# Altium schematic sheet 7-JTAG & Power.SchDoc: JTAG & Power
size B; CompanyName: NGRF; Address1: 2130 Howard Drive W; Address2: North Mankato, MN 56003; Address3: www.nextgenrf.com; Revision: 2; SheetNumber: 7; SheetTotal: 7; ProjName: BytePipe X9002_HDK; SystemEngineer: ELLIOT NELSON
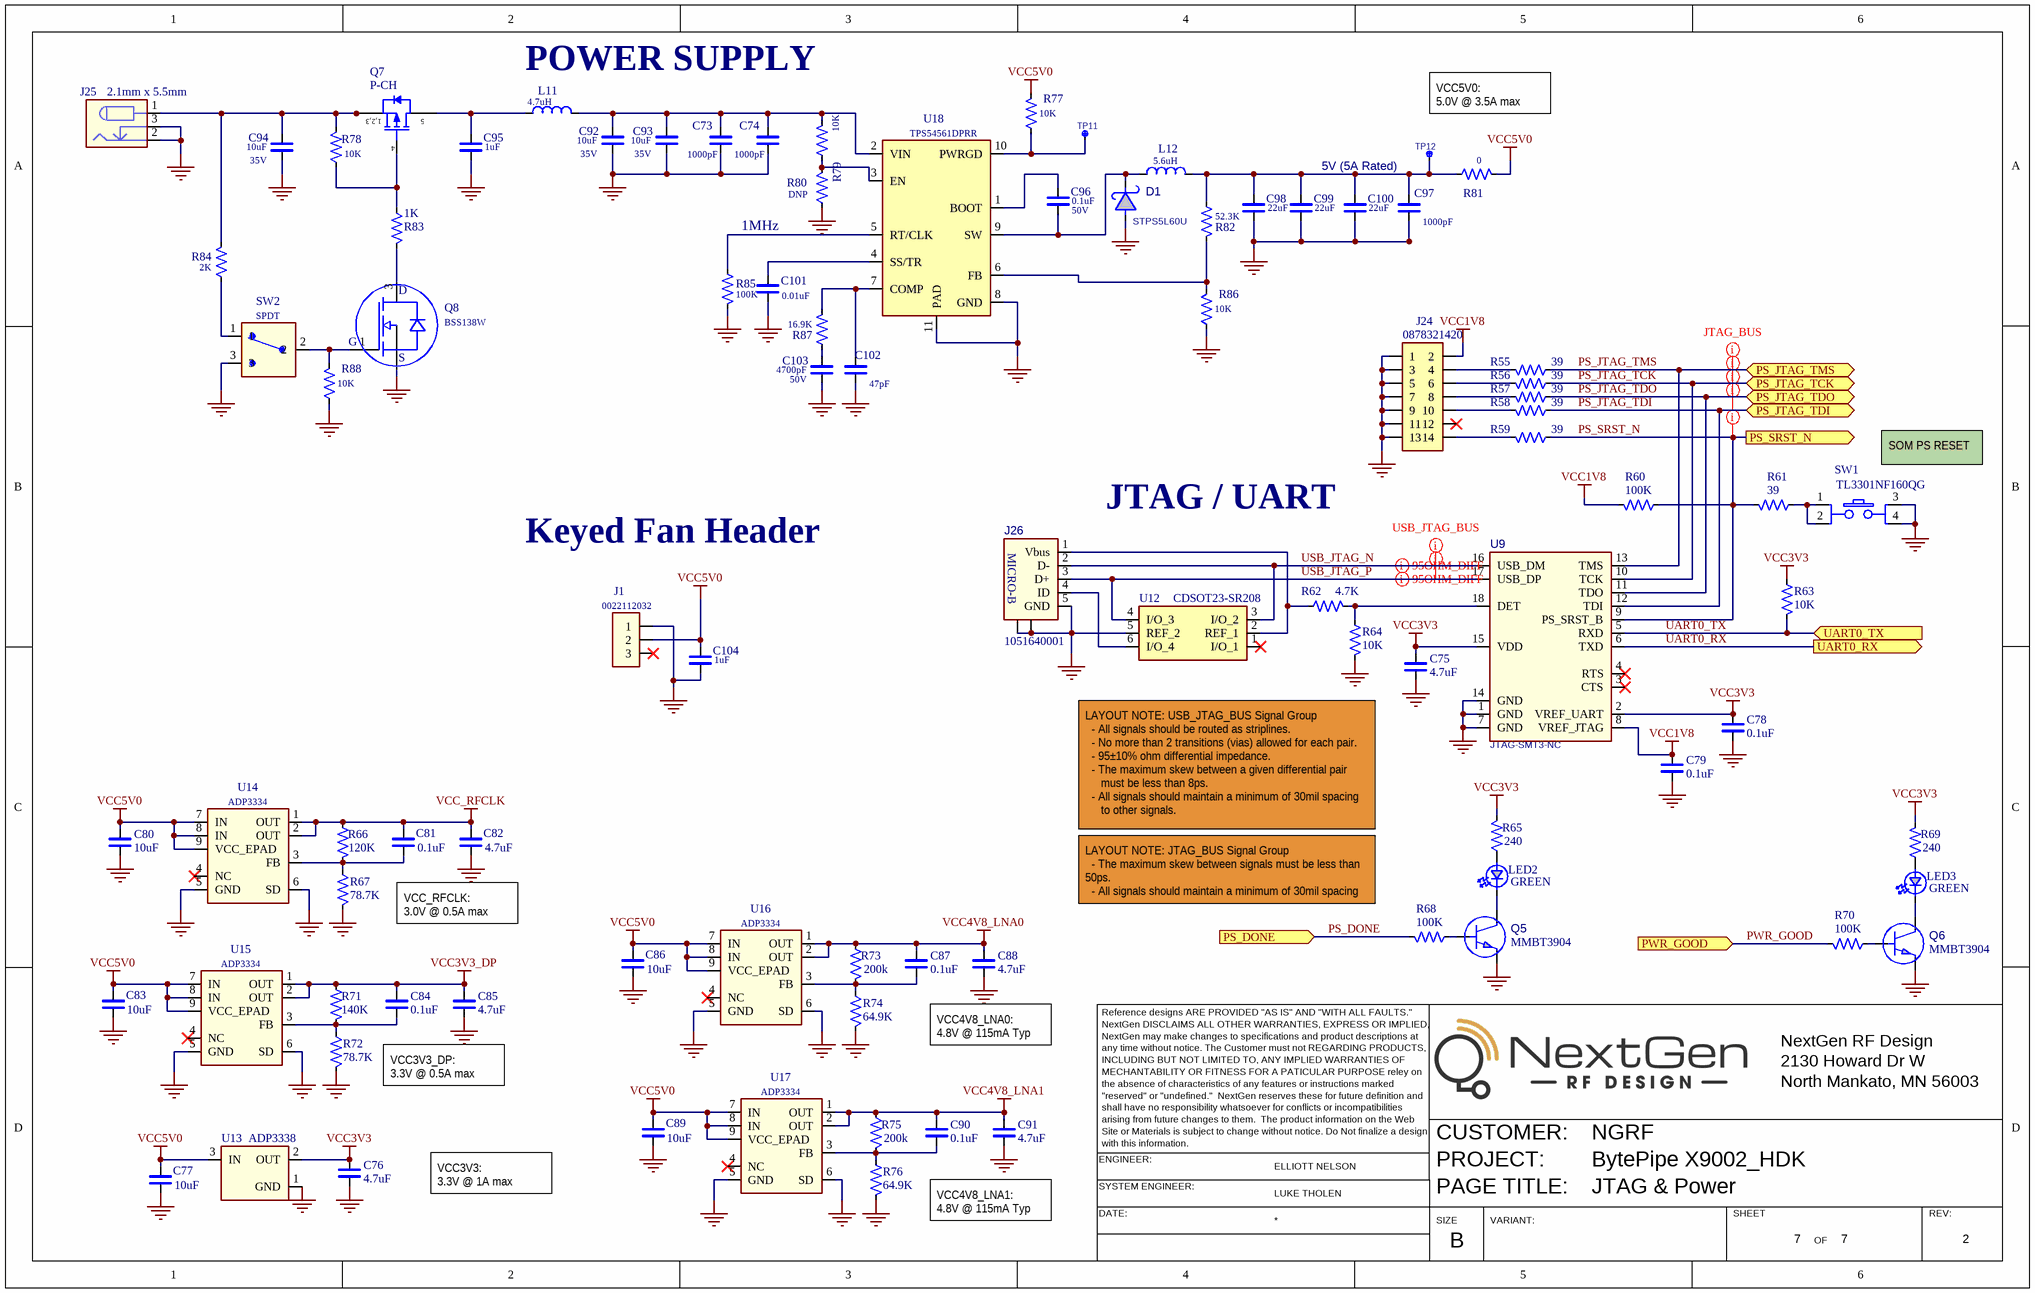
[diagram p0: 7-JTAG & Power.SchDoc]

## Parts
C73  value 1000pF  [SM/0402/CAP]
C74  value 1000pF  [SM/0402/CAP]
C75  value 4.7uF  [SM/0402/CAP]  (hidden comment: CAP_CERAMIC_0402)
C76  value 4.7uF  [SM/0402/CAP]  (hidden comment: CAP_CERAMIC_0402)
C77  value 10uF  [SM/0402/CAP]  (hidden comment: CAP_CERAMIC_0402)
C78  value 0.1uF  [SM/0402/CAP]  (hidden comment: CAP_CERAMIC_0402)
C79  value 0.1uF  [SM/0402/CAP]  (hidden comment: CAP_CERAMIC_0402)
C80  value 10uF  [SM/0402/CAP]  (hidden comment: CAP_CERAMIC_0402)
C81  value 0.1uF  [SM/0402/CAP]  (hidden comment: CAP_CERAMIC_0402)
C82  value 4.7uF  [SM/0402/CAP]  (hidden comment: CAP_CERAMIC_0402)
C83  value 10uF  [SM/0402/CAP]  (hidden comment: CAP_CERAMIC_0402)
C84  value 0.1uF  [SM/0402/CAP]  (hidden comment: CAP_CERAMIC_0402)
C85  value 4.7uF  [SM/0402/CAP]  (hidden comment: CAP_CERAMIC_0402)
C86  value 10uF  [SM/0402/CAP]  (hidden comment: CAP_CERAMIC_0402)
C87  value 0.1uF  [SM/0402/CAP]  (hidden comment: CAP_CERAMIC_0402)
C88  value 4.7uF  [SM/0402/CAP]  (hidden comment: CAP_CERAMIC_0402)
C89  value 10uF  [SM/0402/CAP]  (hidden comment: CAP_CERAMIC_0402)
C90  value 0.1uF  [SM/0402/CAP]  (hidden comment: CAP_CERAMIC_0402)
C91  value 4.7uF  [SM/0402/CAP]  (hidden comment: CAP_CERAMIC_0402)
C92  value 10uF  VOLT: 35V  [SM/0805/CAP]  (hidden comment: CAP_CERAMIC_0805)
C93  value 10uF  VOLT: 35V  [SM/0805/CAP]  (hidden comment: CAP_CERAMIC_0805)
C94  value 10uF  VOLT: 35V  [SM/0805/CAP]  (hidden comment: CAP_CERAMIC_0805)
C95  value 1uF  [SM/0603/CAP]  (hidden comment: CAP_CERAMIC_0603)
C96  value 0.1uF  VOLT: 50V  [SM/0402/CAP]  (hidden comment: CAP_CERAMIC_0402)
C97  value 1000pF  [SM/0402/CAP]
C98  value 22uF  [SM/0805/CAP]  (hidden comment: CAP_CERAMIC_0805)
C99  value 22uF  [SM/0805/CAP]  (hidden comment: CAP_CERAMIC_0805)
C100  value 22uF  [SM/0805/CAP]  (hidden comment: CAP_CERAMIC_0805)
C101  value 0.01uF  [SM/0402/CAP]
C102  value 47pF  [SM/0402/CAP]
C103  value 4700pF  VOLT: 50V  [SM/0402/CAP]
C104  value 1uF  [SM/0603/CAP]  (hidden comment: CAP_CERAMIC_0603)
D1  value STPS5L60U  [SM/DO-214AA/SMB_A]  (hidden comment: DIODE_SCHOTTKY SMB)
J1  0022112032  [CON/MLX/0022112032/3P]
J24  value 0878321420  [SM/CON/MLX/0878321420]  (hidden comment: CON_MOLEX_0878321420_14P)
J25  value 2.1mm x 5.5mm  [CON/WURTH/694106301002]  (hidden comment: CON_WURTH_694106301002)
J26  value 1051640001  [SM/CON/USB/MICRO B RA]  (hidden comment: CON_USB_MICRO-B_RA)
L11  value 4.7uH  [SM/IND/COILCRAFT/XAL4020]  (hidden comment: IND_COILCRAFT_XAL4020)
L12  value 5.6uH  [SM/IND/COILCRAFT/XAL7030]  (hidden comment: IND_COILCRAFT_XAL7030)
LED2  value GREEN  [SM/LED_0603]  (hidden comment: LED_0603)
LED3  value GREEN  [SM/LED_0603]  (hidden comment: LED_0603)
Q5  value MMBT3904  [SM/SOT23_A]  (hidden comment: TRANSISTOR_NPN_SOT23)
Q6  value MMBT3904  [SM/SOT23_A]  (hidden comment: TRANSISTOR_NPN_SOT23)
Q7  value P-CH  [SM/POWERPAK/VISHAY/SO-8]  (hidden comment: MOSFET P-CH 20V 60A PPAK SO-8)
Q8  value BSS138W  [SM/SOT323_A]  (hidden comment: FET_N-CHANNEL_SC70)
R55  value 39  [SM/0402/RES]  (hidden comment: RES_0402_A)
R56  value 39  [SM/0402/RES]  (hidden comment: RES_0402_A)
R57  value 39  [SM/0402/RES]  (hidden comment: RES_0402_A)
R58  value 39  [SM/0402/RES]  (hidden comment: RES_0402_A)
R59  value 39  [SM/0402/RES]  (hidden comment: RES_0402_A)
R60  value 100K  [SM/0402/RES]  (hidden comment: RES_0402_A)
R61  value 39  [SM/0402/RES]  (hidden comment: RES_0402_A)
R62  value 4.7K  [SM/0402/RES]  (hidden comment: RES_0402_A)
R63  value 10K  [SM/0402/RES]  (hidden comment: RES_0402_A)
R64  value 10K  [SM/0402/RES]  (hidden comment: RES_0402_A)
R65  value 240  [SM/0402/RES]  (hidden comment: RES_0402_A)
R66  value 120K  [SM/0402/RES]  (hidden comment: RES_0402_A)
R67  value 78.7K  [SM/0402/RES]  (hidden comment: RES_0402_A)
R68  value 100K  [SM/0402/RES]  (hidden comment: RES_0402_A)
R69  value 240  [SM/0402/RES]  (hidden comment: RES_0402_A)
R70  value 100K  [SM/0402/RES]  (hidden comment: RES_0402_A)
R71  value 140K  [SM/0402/RES]  (hidden comment: RES_0402_A)
R72  value 78.7K  [SM/0402/RES]  (hidden comment: RES_0402_A)
R73  value 200k  [SM/0402/RES]  (hidden comment: RES_0402_A)
R74  value 64.9K  [SM/0402/RES]  (hidden comment: RES_0402_A)
R75  value 200k  [SM/0402/RES]  (hidden comment: RES_0402_A)
R76  value 64.9K  [SM/0402/RES]  (hidden comment: RES_0402_A)
R77  value 10K  [SM/0402/RES]  (hidden comment: RES_0402_A)
R78  value 10K  [SM/0402/RES]  (hidden comment: RES_0402_A)
R79  value 10K  [SM/0402/RES]  (hidden comment: RES_0402_A)
R80  value DNP  [SM/0402/RES]  (hidden comment: RES_0402_A)
R81  value 0  [SM/0805/RES]  (hidden comment: RES_0805_A)
R82  value 52.3K  [SM/0402/RES]  (hidden comment: RES_0402_A)
R83  value 1K  [SM/0402/RES]  (hidden comment: RES_0402_A)
R84  value 2K  [SM/0402/RES]  (hidden comment: RES_0402_A)
R85  value 100K  [SM/0402/RES]  (hidden comment: RES_0402_A)
R86  value 10K  [SM/0402/RES]  (hidden comment: RES_0402_A)
R87  value 16.9K  [SM/0402/RES]  (hidden comment: RES_0402_A)
R88  value 10K  [SM/0402/RES]  (hidden comment: RES_0402_A)
SW1  value TL3301NF160QG  [SM/SWITCH/E-SWITCH/SPST]  (hidden comment: SWITCH_E-SWITCH_TACTILE_SPST)
SW2  value SPDT  [SWITCH/NIDEC/SPDT/AS1D-2M-10-Z]  (hidden comment: AS1D-2M-10-Z)
TP11  TESTPOINT_030  [SM/TESTPOINT/30MIL]  (value not drawn)  (no BOM)
TP12  TESTPOINT_030  [SM/TESTPOINT/30MIL]  (value not drawn)  (no BOM)
U9  value JTAG-SMT3-NC  [SM/MODULE/DIGILENT/JTAG-SMT3]  (hidden comment: MODULE_JTAG-SMT3-NC_18P)
U12  value CDSOT23-SR208  [SM/SOT23-6_C]  (hidden comment: TVS_CDSOT23_SOT23-6_C)
U13  value ADP3338  [SM/SOT223-3_B]  (hidden comment: REG_ADP3338_SOT223-3)
U14  value ADP3334  [SM/DFN8/3x3MM_B]  (hidden comment: REG_ADP334_DFN-8)
U15  value ADP3334  [SM/DFN8/3x3MM_B]  (hidden comment: REG_ADP334_DFN-8)
U16  value ADP3334  [SM/DFN8/3x3MM_B]  (hidden comment: REG_ADP334_DFN-8)
U17  value ADP3334  [SM/DFN8/3x3MM_B]  (hidden comment: REG_ADP334_DFN-8)
U18  value TPS54561DPRR  [SM/WSON10/4x4MM_A]  (hidden comment: REG_TPS54561_WSON-10)

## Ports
PS_DONE (in), PS_JTAG_TCK (bidir), PS_JTAG_TDI (bidir), PS_JTAG_TDO (bidir), PS_JTAG_TMS (bidir), PS_SRST_N (out), PWR_GOOD (in), UART0_RX (out), UART0_TX (in)

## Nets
GND: C73.1(N1) C74.1(N1) C75.2(N2) C76.2(N2) C77.2(N2) C78.2(N2) C79.2(N2) C80.2(N2) C82.2(N2) C83.2(N2) C85.2(N2) C86.2(N2) C88.2(N2) C89.2(N2) C91.2(N2) C92.2(N2) C93.2(N2) C94.2(N2) C95.2(N2) C97.1(N1) C98.2(N2) C99.2(N2) C100.2(N2) C101.1(N1) C102.1(N1) C103.2(N2) C104.2(N2) D1.2(A) J1.1 J24.1 J24.3 J24.5 J24.7 J24.9 J24.11 J24.13 J25.2 J25.3 J26.5(GND) J26.SH J26.TH Q5.2(E) Q6.2(E) Q8.2(SOURCE) R64.2 R67.1 R72.1 R74.1 R76.1 R80.1 R85.2 R86.2 R88.2 SW1.3 SW1.4 SW2.3 U9.1(GND) U9.7(GND) U9.14(GND) U12.5(REF_2) U13.1(GND) U14.5(GND) U14.6(SD) U15.5(GND) U15.6(SD) U16.5(GND) U16.6(SD) U17.5(GND) U17.6(SD) U18.8(GND) U18.11(PAD)
VCC1V8: C79.1(N1) J24.2 R60.2 U9.8(VREF_JTAG)
VCC3V3: C75.1(N1) C76.1(N1) C78.1(N1) R63.1 R65.1 R69.1 U9.2(VREF_UART) U9.15(VDD) U13.2(OUT)
VCC3V3_DP: C84.1(N1) C85.1(N1) R71.2 U15.1(OUT) U15.2(OUT)
VCC4V8_LNA0: C87.1(N1) C88.1(N1) R73.2 U16.1(OUT) U16.2(OUT)
VCC4V8_LNA1: C90.1(N1) C91.1(N1) R75.2 U17.1(OUT) U17.2(OUT)
VCC5V0: C77.1(N1) C80.1(N1) C83.1(N1) C86.1(N1) C89.1(N1) C104.1(N1) J1.2 R77.1 R81.2 U13.3(IN) U14.7(IN) U14.8(IN) U14.9(VCC_EPAD) U15.7(IN) U15.8(IN) U15.9(VCC_EPAD) U16.7(IN) U16.8(IN) U16.9(VCC_EPAD) U17.7(IN) U17.8(IN) U17.9(VCC_EPAD)
VCC_RFCLK: C81.1(N1) C82.1(N1) R66.2 U14.1(OUT) U14.2(OUT)
PS_DONE: R68.2 ; port PS_DONE
PS_JTAG_TCK: R56.1 U9.10(TCK) ; port PS_JTAG_TCK
PS_JTAG_TDI: R58.1 U9.12(TDI) ; port PS_JTAG_TDI
PS_JTAG_TDO: R57.1 U9.11(TDO) ; port PS_JTAG_TDO
PS_JTAG_TMS: R55.1 U9.13(TMS) ; port PS_JTAG_TMS
PS_SRST_N: R59.1 R60.1 R61.2 U9.9(PS_SRST_B) ; port PS_SRST_N
PWR_GOOD: R70.2 ; port PWR_GOOD
UART0_RX: U9.6(TXD) ; port UART0_RX
UART0_TX: R63.2 U9.5(RXD) ; port UART0_TX
USB_JTAG_N: J26.2(D-) U9.16(USB_DM) U12.3(I/O_2)
USB_JTAG_P: J26.3(D+) U9.17(USB_DP) U12.4(I/O_3)
NetC73_2: C73.2(N2) C74.2(N2) C92.1(N1) C93.1(N1) L11.2(N2) R79.2 U18.2(VIN)
NetC81_2: C81.2(N2) R66.1 R67.2 U14.3(FB)
NetC84_2: C84.2(N2) R71.1 R72.2 U15.3(FB)
NetC87_2: C87.2(N2) R73.1 R74.2 U16.3(FB)
NetC90_2: C90.2(N2) R75.1 R76.2 U17.3(FB)
NetC94_1: C94.1(N1) J25.1 Q7.1(SOURCE) Q7.2(SOURCE) Q7.3(SOURCE) R78.1 R84.1
NetC95_1: C95.1(N1) L11.1(N1) Q7.5(DRAIN)
NetC96_1: C96.1(N1) U18.1(BOOT)
NetC96_2: C96.2(N2) D1.1(K) L12.1(N1) U18.9(SW)
NetC97_2: C97.2(N2) C98.1(N1) C99.1(N1) C100.1(N1) L12.2(N2) R81.1 R82.2 TP12.1(N1)
NetC101_2: C101.2(N2) U18.4(SS/TR)
NetC102_2: C102.2(N2) R87.2 U18.7(COMP)
NetC103_1: C103.1(N1) R87.1
NetJ24_4: J24.4 R55.2
NetJ24_6: J24.6 R56.2
NetJ24_8: J24.8 R57.2
NetJ24_10: J24.10 R58.2
NetJ24_14: J24.14 R59.2
NetJ26_1: J26.1(Vbus) R62.1 U12.2(REF_1)
NetJ26_4: J26.4(ID) U12.6(I/O_4)
NetLED2_1: LED2.1(C) Q5.3(C)
NetLED2_2: LED2.2(A) R65.2
NetLED3_1: LED3.1(C) Q6.3(C)
NetLED3_2: LED3.2(A) R69.2
NetQ5_1: Q5.1(B) R68.1
NetQ6_1: Q6.1(B) R70.1
NetQ7_4: Q7.4(GATE) R78.2 R83.1
NetQ8_1: Q8.1(GATE) R88.1 SW2.2
NetQ8_3: Q8.3(DRAIN) R83.2
NetR61_1: R61.1 SW1.1 SW1.2
NetR62_2: R62.2 R64.1 U9.18(DET)
NetR77_2: R77.2 TP11.1(N1) U18.10(PWRGD)
NetR79_1: R79.1 R80.2 U18.3(EN)
NetR82_1: R82.1 R86.1 U18.6(FB)
NetR84_2: R84.2 SW2.1
NetR85_1: R85.1 U18.5(RT/CLK)

Not connected (* = marked no-connect by the designer): J1 3*; J24 12*; U9 3(CTS)* 4(RTS)*; U12 1(I/O_1)*; U14 4(NC)*; U15 4(NC)*; U16 4(NC)*; U17 4(NC)*

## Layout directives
net class USB_JTAG_BUS: USB_JTAG_N, USB_JTAG_P
net class JTAG_BUS: PS_JTAG_TCK, PS_JTAG_TDI, PS_JTAG_TDO, PS_JTAG_TMS, PS_SRST_N
differential pair; Impedance: 90 Ohms; differential pair class 95OHM_DIFF: USB_JTAG_N, USB_JTAG_P

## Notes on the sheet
- (near L11) POWER SUPPLY
- VCC5V0:
  5.0V @ 3.5A max
- 1MHz
- 5V (5A Rated)
- (near SW1) SOM PS RESET
- Keyed Fan Header
- JTAG / UART
- LAYOUT NOTE: USB_JTAG_BUS Signal Group
  - All signals should be routed as striplines.
  - No more than 2 transitions (vias) allowed for each pair.
  - 95±10% ohm differential impedance.
  - The maximum skew between a given differential pair
  must be less than 8ps.
  - All signals should maintain a minimum of 30mil spacing
  to other signals.
- (near R68) LAYOUT NOTE: JTAG_BUS Signal Group
  - The maximum skew between signals must be less than 50ps.
  - All signals should maintain a minimum of 30mil spacing to
  other signals outside this signal group.
- VCC_RFCLK:
  3.0V @ 0.5A max
- VCC4V8_LNA0:
  4.8V @ 115mA Typ
- Reference designs ARE PROVIDED "AS IS" AND "WITH ALL FAULTS."
- NextGen DISCLAIMS ALL OTHER WARRANTIES, EXPRESS OR IMPLIED,
- NextGen may make changes to specifications and product descriptions at
- NextGen RF Design
- VCC3V3_DP:
  3.3V @ 0.5A max
- any time without notice. The Customer must not REGARDING PRODUCTS,
- INCLUDING BUT NOT LIMITED TO, ANY IMPLIED WARRANTIES OF
- MECHANTABILITY OR FITNESS FOR A PATICULAR PURPOSE reley on
- "reserved" or "undefined."  NextGen reserves these for future definition and
- the absence of characteristics of any features or instructions marked
- shall have no responsibility whatsoever for conflicts or incompatibilities
- 2130 Howard Dr W
- North Mankato, MN 56003
- ENGINEER:
- Site or Materials is subject to change without notice. Do Not finalize a design
- with this information.
- arising from future changes to them.  The product information on the Web
- ELLIOTT NELSON
- CUSTOMER:
- PROJECT:
- VCC3V3:
  3.3V @ 1A max
- VCC4V8_LNA1:
  4.8V @ 115mA Typ
- SYSTEM ENGINEER:
- DATE:
- LUKE THOLEN
- SIZE
- PAGE TITLE:
- VARIANT:
- SHEET
- OF
- REV:
- B

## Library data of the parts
C73 C74 C97 = CAP_CERAMIC_0402: CAP CER 1000PF 50V C0G/NP0 0402; TOL: 1%; OEM#: GRM1555C1H102FA01D; OEM NAME: Murata Electronics
C75 C76 C82 C85 C88 C91 = CAP_CERAMIC_0402: CAP CER 4.7UF 10V X5R 0402; TOL: ±20%; OEM#: CL05A475MP5NRNC; OEM NAME: Samsung
C77 C80 C83 C86 C89 = CAP_CERAMIC_0402: 10µF ±20% 10V Ceramic Capacitor X5R 0402 (1005 Metric); OEM#: CL05A106MP8NUB8; OEM NAME: Samsung
C78 C79 C81 C84 C87 C90 = CAP_CERAMIC_0402: CAP CER 0.1UF 25V X7R 0402; TOL: ±10%; OEM#: CL05B104KA5NNNC; OEM NAME: Samsung
C92 C93 = CAP_CERAMIC_0805: CAP CER 10UF 35V X5R 0805; OEM#: GRM21BR6YA106ME43L; OEM NAME: Murata Electronics; TOL: 20%
C94 = CAP_CERAMIC_0805: CAP CER 10UF 35V X5R 0805; OEM#: GMK212BBJ106MG-T; OEM NAME: Taiyo Yuden; TOL: 20%
C95 C104 = CAP_CERAMIC_0603: TOL: 10%; OEM#: GRT188R61H105KE13D; OEM NAME: Murata; VOLT: 50V
C96 = CAP_CERAMIC_0402: CAP CER 0.1UF 50V X7R 0402; TOL: 10%; OEM#: CGA2B3X7R1H104K050BB; OEM NAME: TDK Corporation
C98-C100 = CAP_CERAMIC_0805: CAP CER 22UF 16V X5R 0805; OEM#: GRM219R61C226ME15L; OEM NAME: Murata Electronics; TOL: 20%
C101 = CAP_CERAMIC_0402: CAP CER 10000PF 50V X7R 0402; TOL: 10%; OEM#: GCM155R71H103KA55J; OEM NAME: Murata Electronics
C102 = CAP_CERAMIC_0402: CAP CER 47PF 50V C0G/NP0 0402; TOL: 5%; OEM#: GCM1555C1H470JA16D; OEM NAME: Murata Electronics
C103 = CAP_CERAMIC_0402: CAP CER 4700PF 50V X7R 0402; TOL: 10%; OEM#: GRM155R71H472KA01J; OEM NAME: Murata
D1 = DIODE_SCHOTTKY SMB: DIODE SCHOTTKY 60V 5A SMB; OEM NAME: STMicroelectronics
J1 = CON_100SP_1X3P_MLX_KK100: Connector Header Through Hole 3 position 0.100" (2.54mm).  Molex KK 100 Series.
J24 = CON_MOLEX_0878321420_14P: Connector Header Surface Mount 14 position 0.079" (2.00mm); OEM NAME: MOLEX
J25 = CON_WURTH_694106301002: Wurth DC power jack, 2.1mm pin, right angle
J26 = CON_USB_MICRO-B_RA: USB MICRO-B RIGHT ANGLE, MOLEX 1051640001; OEM NAME: Molex, LLC
L11 = IND_COILCRAFT_XAL4020: Fixed Inductors 4.7uH 20% 5.1A 44.1mOhms AEC-Q200; OEM#: XAL4030-472MEC
L12 = IND_COILCRAFT_XAL7030: OEM#: XAL7030-562MEC
LED2 LED3 = LED_0603: LED-0603; OEM#: LG L29K-F2J1-24-Z; OEM NAME: OSRAM
Q5 Q6 = TRANSISTOR_NPN_SOT23: Bipolar (BJT) Transistor NPN 40V 200mA 300MHz 300mW Surface Mount SOT-23-3 (TO-236); OEM#: MMBT3904LT1G; OEM NAME: ON Semiconductor
Q7 = FET_P-CHANNEL_PPAK-SO-8: P-Channel 20 V 60A (Tc) 6.25W (Ta), 104W (Tc) Surface Mount PowerPAK® SO-8; OEM NAME: VISHAY SILICONIX; OEM#: SI7157DP-T1-GE3
Q8 = FET_N-CHANNEL_SC70: FET, N-Channel, SC70/SOT323; OEM NAME: ON Semi
R55-R59 R61 = RES_0402_A: RES SMD 39 OHM 1% 1/10W 0402; OEM#: ERJ-2RKF39R0X; OEM NAME: Panasonic
R60 R68 R70 R85 = RES_0402_A: RES SMD 100K OHM 1% 1/10W 0402; OEM#: ERJ-2RKF1003X; OEM NAME: Panasonic
R62 = RES_0402_A: RES SMD 4.7K OHM 1% 1/10W 0402; OEM#: ERJ-2RKF4701X; OEM NAME: Panasonic
R63 R64 = RES_0402_A: OEM#: ERJ-2RKF1002X; OEM NAME: Panasonic; TOL: ±1%
R65 R69 = RES_0402_A: RES SMD 240 OHM 1% 1/10W 0402; OEM#: ERJ-2RKF2400X; OEM NAME: Panasonic
R66 = RES_0402_A: RES 120K OHM 1% 1/10W 0402 SMD; OEM#: ERJ-2RKF1203X; OEM NAME: Panasonic
R67 R72 = RES_0402_A: RES SMD 78.7K OHM 1% 1/10W 0402; OEM#: ERJ-2RKF7872X; OEM NAME: Panasonic
R71 = RES_0402_A: RES SMD 140K OHM 1% 1/10W 0402; OEM#: ERJ-2RKF1403X; OEM NAME: Panasonic
R73 R75 = RES_0402_A: RES SMD 200K OHM 1% 1/10W 0402; OEM#: ERJ-2RKF2003X; OEM NAME: Panasonic
R74 R76 = RES_0402_A: RES SMD 64.9K OHM 1% 1/10W 0402; OEM#: ERJ-2RKF6492X; OEM NAME: Panasonic
R77-R79 R86 R88 = RES_0402_A: RES SMD 10K OHM 1% 1/10W 0402; OEM#: ERJ-2RKF1002X; OEM NAME: Panasonic
R80 = RES_0402_A: DNP; OEM NAME: Panasonic
R81 = RES_0805_A: RES SMD 0 OHM JUMPER 1/8W 0805; OEM#: ERJ-6GEY0R00V; OEM NAME: Panasonic
R82 = RES_0402_A: RES SMD 52.3K OHM 1% 1/10W 0402; OEM#: ERJ-2RKF5232X; OEM NAME: Panasonic
R83 = RES_0402_A: RES SMD 1K OHM 1% 1/10W 0402; OEM#: ERJ-2RKF1001X; OEM NAME: Panasonic
R84 = RES_0402_A: RES SMD 2 KOHM 1% 1/5W 0402; OEM#: ERJ-PA2F2001X; OEM NAME: Panasonic Electronic Components
R87 = RES_0402_A: RES SMD 16.9K OHM 1% 1/10W 0402; OEM#: ERJ-2RKF1692X; OEM NAME: Panasonic
SW1 = SWITCH_E-SWITCH_TACTILE_SPST: Tactile Switch SPST-NO Top Actuated Surface Mount
SW2 = SWITCH_SLIDE_NIDEC_SPDT: SWITCH SLIDE SPDT 50MA 48V; OEM NAME: Nidec Copal Electronics
U9 = MODULE_JTAG-SMT3-NC_18P: SMT Programming module for Xilinx FPGAs.; OEM NAME: DIGILENT
U12 = TVS_CDSOT23_SOT23-6_C: Clamp Ipp Tvs Diode Surface Mount SOT-23-6.; OEM NAME: Bourns Inc.
U13 = REG_ADP3338_SOT223-3: Linear Voltage Regulator IC 3.3V Output 1A SOT-223-3; OEM NAME: ANALOG DEVICES; OEM#: ADP3338AKCZ-3.3-RL
U14-U17 = REG_ADP334_DFN-8: Linear Voltage Regulator IC  1 Output  500mA 8-LFCSP-WD (3x3); OEM#: ADP3334ACPZ-REEL7; OEM NAME: ANALOG DEVICES
U18 = REG_TPS54561_WSON-10: 4.5-V to 60-V Input, 5-A, Step-Down DC-DC Converter with Soft-Start and Eco-mode; OEM NAME: Texas Instruments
